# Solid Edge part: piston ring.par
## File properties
Author: Robert a Rhodes jr
Template: Normal.par
Last saved by: CADCIM
Revision: 8
Application: Solid Edge
Accuracy: 0.99
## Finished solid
Body 1: solid body, 6 faces, 12 edges, 8 vertices.
  Faces by surface: plane 4, cylinder 2
  Edges by curve: line 8, circle 4
Bounding box of the edges (mm): 94.000 x 94.000 x 3.000, from (-47, -47, -3) to (47, 47, 0).
Cylindrical faces by radius (mm): R43 x1, R47 x1
Planar faces by outward normal: +y 1, +z 1, -y 1, -z 1
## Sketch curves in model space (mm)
line (-28.0593, 0, 0) -> (-28.0593, -1, 0)
line (-28.0593, -1, 0) -> (-54.5597, -1, 0)
line (-54.5597, -1, 0) -> (-54.5597, 0, 0)
line (-54.5597, 0, 0) -> (-28.0593, 0, 0)
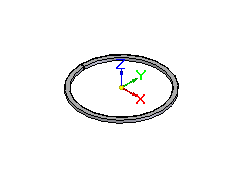
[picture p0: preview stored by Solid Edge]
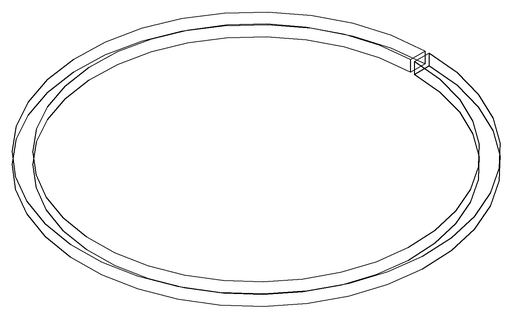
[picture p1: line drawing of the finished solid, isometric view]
